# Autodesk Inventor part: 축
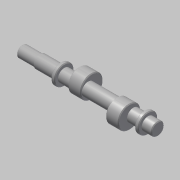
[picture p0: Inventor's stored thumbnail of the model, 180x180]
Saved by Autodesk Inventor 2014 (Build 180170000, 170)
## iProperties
Created: 2013-02
Part Number: 축
Document SubType Name: Modeling
Designer: 한국산업디자인학원[gmhk.co.kr]
Density: 7.86 g/cm^3
Material: 강철, 연강
Mass: 458.535 g
Surface Area: 143.366 cm^2
Volume: 58.3378 cm^3
Appearance: 강철
Author: 한국산업디자인학원[gmhk.co.kr]
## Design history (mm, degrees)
sketch "스케치2"
  geometry: L1 (-58, 84.5)-(-58, 15.5) reference; L2 (58, 15.5)-(58, 84.5) reference; L3 (-85, 25.774)-(-85, 74.226) reference; L4 (70, 84.185)-(70, 15.815) reference; L5 (71, 50)-(-109, 50); L6 (69.4, 58.5)-(58.6, 58.5) reference; L7 (71, 50)-(71, 58.5); L8 (71, 58.5)-(58, 58.5); L9 (58, 58.5)-(58, 63); L10 (58, 63)-(53, 63); L11 (53, 63)-(53, 58.5); L12 (53, 58.5)-(-53, 58.5); L13 (-53, 58.5)-(-53, 63); L14 (-53, 63)-(-58, 63); L15 (-58, 63)-(-58, 58.5); L16 (-58, 58.5)-(-85, 58.5); L17 (-85, 58.5)-(-85, 57.5); L18 (-85, 57.5)-(-109, 57.5); L19 (-109, 57.5)-(-109, 50); L20 (-30, 102.5)-(-30, 50); L21 (30, 102.5)-(30, 50); L22 (-50, 102.5)-(-10, 102.5) reference; L23 (10, 102.5)-(50, 102.5) reference; 2 further points
  constraints: 34 end point, 10 perpendicular, 9 point on line, 5 collinear, 3 midpoint, 3 parallel, 1 horizontal, 2 other
  dimensions: "d0" = 1 distance between parallel lines of L7 L4; "d1" = 26 diameter of L10 L5; "d2" = 5 distance of L9.end L10.end; "d3" = 5 distance of L13.end L14.end (= d2); "d4" = 180 distance of L5.start L5.end; "d5" = 15 diameter of L18 L5
  node "참조1"
  node "참조2"
  node "참조3"
  node "참조4"
  node "참조7"
  node "참조8"
revolve "회전1" stored, may be unused: angle "d6" = 90 deg
node "작업 평면1"
sketch "스케치3"
  geometry: C1 r 8.5 at (52.5, 0) reference; C2 r 15 at (47.5, 0); 1 further point
  constraints: 1 centre point, 1 horizontal alignment
  dimensions: "d8" = 5 distance of C1.centre C2.centre; "d9" = 30 diameter of C2
extrude "돌출1" join sketch "스케치3" stored distance "d10" = 17; taper "d11" = 0 deg
node "작업 평면2"
sketch "스케치4"
  geometry: C1 r 8.5 at (52.5, 0) reference; C2 r 15 at (57.5, 0); 1 further point
  constraints: 1 centre point, 1 horizontal alignment
  dimensions: "d13" = 5 distance of C2.centre C1.centre; "d14" = 30 diameter of C2
extrude "돌출2" join sketch "스케치4" stored distance "d15" = 17; taper "d16" = 0 deg
chamfer "모따기1" distance "d17" = 1; stored, may be unused: second distance "d18" = 2, angle "d19" = 45 deg
node "작업 평면3"
sketch "스케치5"
  geometry: L1 (12, 6.5)-(12, -6.5) reference; L2 (12, 2.5)-(-5.5, 2.5); L3 (-5.5, -2.5)-(12, -2.5); A1 r 2.5 centre (-5.5, 0) between (-5.5, 2.5) and (-5.5, -2.5); 2 further points
  constraints: 4 end point, 2 point on circle, 2 point on line, 2 tangent, 1 centre point, 1 horizontal alignment, 1 midpoint, 1 parallel, 1 perpendicular
  dimensions: "d20" = 5 distance between parallel lines of L3 L2; "d21" = 20 dimension on A1 L1
extrude "돌출3" cut sketch "스케치5" distance "d22" = 3; taper "d23" = 0 deg
chamfer "모따기2" distance "d24" = 1; stored, may be unused: second distance "d25" = 2, angle "d26" = 45 deg
node "솔리드1"
node "투영된 루프1"
node "투영된 루프2"
other parameters: "d7" = 0, "d12" = 0
